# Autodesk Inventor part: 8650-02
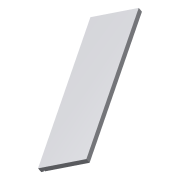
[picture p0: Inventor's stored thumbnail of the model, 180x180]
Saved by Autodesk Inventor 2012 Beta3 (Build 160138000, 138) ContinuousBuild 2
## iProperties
Created: 2011-02
Part Number: 8650-02
Material: Default
Document SubType Name: Modeling
Designer: Beta-8540w
Density: 1 g/cm^3
Author: Beta-8540w
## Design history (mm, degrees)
derived "c15-13.ipt" dims "d2" = 12.7, "d3" = 0, "d4" = 6.35, "d6" = 3.302, "d7" = 0, "drawer_depth" = 412.75, "drawer_side_height" = 127, "bottom_thickness" = 3.302
body "Solid1"
feature "Solid1::c15-13.ipt" dims "d2" = 12.7, "d3" = 0, "d4" = 6.35, "d6" = 3.302, "d7" = 0, "drawer_depth" = 412.75, "drawer_side_height" = 127, "bottom_thickness" = 3.302, "ScaleForDerivedMember" = 10
tag "TaggingFeature1"
